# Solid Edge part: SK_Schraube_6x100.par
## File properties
Author: fknapp
Template: Iso Metric Part.par
Last saved by: fknapp
Revision: 16
Application: Solid Edge
Username: fknapp
Genauigkeit: 0,990
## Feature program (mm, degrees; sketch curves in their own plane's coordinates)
sketch for "unnamed RevolvedProtrusion 1" plane through (0, 0, 0) normal (1, 0, 0) x-axis (0, 1, 0)
  line (0, -100) -> (3, -94.8038)
  line (3, -94.8038) -> (3, -3.5)
  line (5.5, -1) -> (3, -3.5)
  line (5.5, 0) -> (5.5, -1)
  line (5.5, 0) -> (0, 0)
  dimension (linear) = 5.5
  dimension (linear) = 5.5
revolve "unnamed RevolvedProtrusion 1" add full turn 360 deg about sketch line (0, 0) -> (0, -100)
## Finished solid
Body 1: solid body, 5 faces, 4 edges, 1 vertex.
  Faces by surface: cone 2, cylinder 2, plane 1
  Edges by curve: circle 4
Bounding box of the edges (mm): 11.000 x 11.000 x 94.804, from (-5.5, -5.5, -94.8038) to (5.5, 5.5, 0).
Cylindrical faces by radius (mm): R3 x1, R5.5 x1
Conical faces (half-angle, radius in mm at the cone's reference point): 30 deg R0 x1, 45 deg R3 x1
Planar faces by outward normal: +z 1
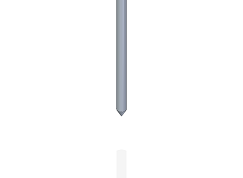
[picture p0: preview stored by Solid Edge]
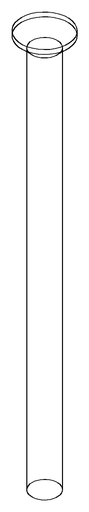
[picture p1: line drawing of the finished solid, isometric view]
